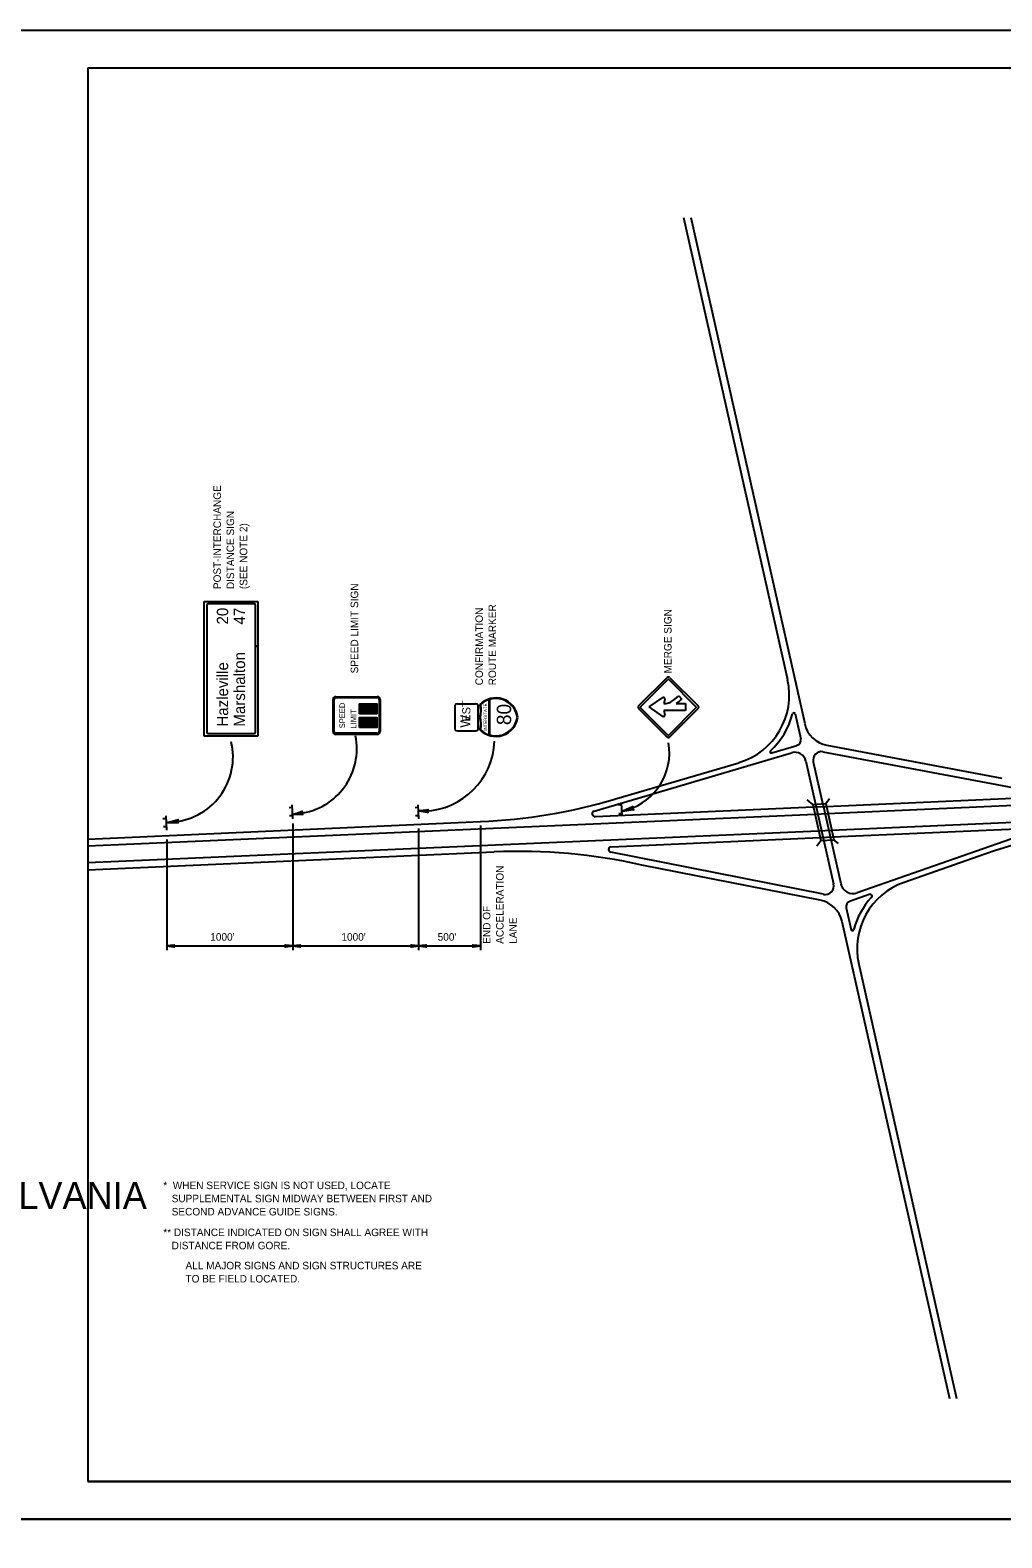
# Model space of a CAD drawing. Extents: x 644898 to 648326, y 298294 to 300670.
# Drawn here: x 645756 to 646144, y 300069 to 300670 of the extents above; entities that cross this region are included whole.
import ezdxf

# ---------------------------------------------------------------- set-up
doc = ezdxf.new("R2010")
doc.units = 0
for name, color, linetype in [('1', 7, 'Continuous'), ('2', 7, 'Continuous'), ('3', 7, 'Continuous'), ('XCS-GRID-MIN', 7, 'Continuous')]:
    doc.layers.add(name, color=color, linetype=linetype)

# ---------------------------------------------------------------- blocks, each defined once
blk = doc.blocks.new('RARROW')
at = {"layer": '3'}
blk.add_lwpolyline([(-2.2695, 0.285), (-2.184875, 0.12075), (0, 0), (-2.2695, 0.285), (-2.38575, 0.384625), (0, 0), (-2.183125, -0.108), (-2.262875, -0.2705), (0, 0), (-2.38575, -0.379125), (-2.262875, -0.2705)], dxfattribs=at)

msp = doc.modelspace()

# ---------------------------------------------------------------- linework, layer by layer
at = {"layer": '1'}
for p, q in [((645779.32, 300655.49), (646565.32, 300655.49)), ((645779.32, 300655.49), (645779.32, 300091.49)), ((646565.32, 300091.49), (645779.32, 300091.49)), ((645779.32, 300091.49), (646365.32, 300091.49))]:
    msp.add_line(p, q, dxfattribs=at)
at = {"layer": '2'}
for p, q in [((646016.95, 300595.74), (646058.45, 300411.37)), ((646019.95, 300595.74), (646065.32, 300393.87)), ((645825.82, 300388.87), (645825.82, 300442.62)), ((645825.82, 300442.62), (645847.2, 300442.62)), ((645826.82, 300441.12), (645826.82, 300390.37)), ((645845.7, 300441.62), (645827.32, 300441.62)), ((645846.2, 300424.75), (645846.2, 300441.12)), ((645847.2, 300442.62), (645847.2, 300424.75)), ((645846.2, 300424.75), (645847.2, 300424.75)), ((645847.2, 300424.75), (645846.2, 300424.75)), ((645846.2, 300390.37), (645846.2, 300424.75)), ((645847.2, 300424.75), (645847.2, 300388.87)), ((645836.45, 300415.74), (645836.45, 300415.74)), ((645999.07, 300400.87), (646010.45, 300412.24)), ((645999.82, 300400.49), (646010.7, 300411.37)), ((646011.07, 300411.37), (646021.95, 300400.49)), ((646011.45, 300412.24), (646022.82, 300400.87)), ((645877.2, 300390.74), (645877.2, 300403.49)), ((645877.57, 300390.74), (645877.57, 300403.49)), ((645878.32, 300404.49), (645894.82, 300404.49)), ((645878.32, 300404.24), (645894.82, 300404.24)), ((645891.7, 300397.74), (645887.7, 300401.74)), ((645892.45, 300397.74), (645888.45, 300401.74)), ((645893.07, 300397.74), (645889.07, 300401.74)), ((645893.82, 300397.74), (645889.82, 300401.74)), ((645894.45, 300397.74), (645890.45, 300401.74)), ((645894.7, 300398.24), (645891.2, 300401.74)), ((645894.7, 300398.99), (645891.95, 300401.74)), ((645894.7, 300399.62), (645892.7, 300401.74)), ((645894.7, 300400.24), (645893.32, 300401.74)), ((645894.7, 300400.99), (645894.07, 300401.74)), ((645895.57, 300403.49), (645895.57, 300390.74)), ((645895.95, 300403.49), (645895.95, 300390.74)), ((645925.95, 300391.49), (645925.95, 300401.24)), ((645926.82, 300401.74), (645933.95, 300401.74)), ((645934.95, 300401.24), (645934.95, 300391.49)), ((645935.95, 300401.37), (645935.95, 300401.37)), ((645939.45, 300389.37), (645939.45, 300403.49)), ((645939.7, 300389.37), (645939.7, 300403.49)), ((646003.32, 300400.49), (646008.7, 300404.24)), ((646009.57, 300403.49), (646009.07, 300401.87)), ((646009.07, 300401.87), (646009.45, 300401.87)), ((646014.07, 300401.87), (646017.82, 300401.87)), ((646015.07, 300404.87), (646016.32, 300403.62)), ((646017.82, 300401.87), (646017.82, 300399.12)), ((645886.57, 300396.99), (645886.57, 300396.99)), ((645890.95, 300397.74), (645887.7, 300401.12)), ((645890.2, 300397.74), (645887.7, 300400.37)), ((645889.57, 300397.74), (645887.7, 300399.74)), ((645888.95, 300397.74), (645887.7, 300398.99)), ((645888.2, 300397.74), (645887.7, 300398.24)), ((645891.7, 300392.24), (645887.7, 300396.24)), ((645890.95, 300392.24), (645887.7, 300395.62)), ((645892.45, 300392.24), (645888.45, 300396.24)), ((645893.07, 300392.24), (645889.07, 300396.24)), ((645893.82, 300392.24), (645889.82, 300396.24)), ((645894.45, 300392.24), (645890.45, 300396.24)), ((645894.7, 300392.74), (645891.2, 300396.24)), ((645894.7, 300393.49), (645891.95, 300396.24)), ((645894.7, 300394.12), (645892.7, 300396.24)), ((645894.7, 300394.74), (645893.32, 300396.24)), ((645894.7, 300395.49), (645894.07, 300396.24)), ((645930.45, 300396.37), (645930.45, 300396.37)), ((645935.95, 300396.37), (645935.95, 300396.37)), ((645943.32, 300396.37), (645943.32, 300396.37)), ((646010.45, 300388.49), (645999.07, 300399.87)), ((646010.7, 300389.24), (645999.82, 300400.12)), ((646008.7, 300396.74), (646003.32, 300400.49)), ((646017.82, 300399.12), (646009.07, 300399.12)), ((646009.07, 300399.12), (646009.57, 300397.49)), ((646021.95, 300400.12), (646011.07, 300389.24)), ((646021.95, 300400.12), (646011.07, 300389.24)), ((646022.82, 300399.87), (646011.45, 300388.49)), ((646061.57, 300397.74), (646063.82, 300387.74)), ((645827.32, 300389.87), (645845.7, 300389.87)), ((645894.82, 300389.99), (645878.32, 300389.99)), ((645894.82, 300389.49), (645878.32, 300389.49)), ((645890.2, 300392.24), (645887.7, 300394.87)), ((645889.57, 300392.24), (645887.7, 300394.24)), ((645888.95, 300392.24), (645887.7, 300393.49)), ((645888.2, 300392.24), (645887.7, 300392.74)), ((645933.95, 300390.87), (645926.82, 300390.87)), ((645935.95, 300391.37), (645935.95, 300391.37)), ((645847.2, 300388.87), (645825.82, 300388.87)), ((646052.2, 300382.12), (646062.2, 300385.12)), ((646074.2, 300385.24), (646143.95, 300372.12)), ((645981.32, 300358.87), (646060.07, 300382.24)), ((645989.45, 300363.74), (646039.07, 300378.24)), ((646065.79, 300378.91), (646069.57, 300361.74)), ((646068.74, 300378.57), (646072.57, 300361.62)), ((646072.57, 300382.62), (646157.57, 300366.62)), ((646074.45, 300357.99), (646565.32, 300379.71)), ((646075.95, 300351.37), (646565.32, 300372.83)), ((645860.7, 300360.37), (645859.7, 300360.24)), ((645860.7, 300361.37), (645860.95, 300355.87)), ((645910.95, 300360.37), (645909.95, 300360.24)), ((645910.95, 300361.37), (645911.2, 300355.87)), ((645981.7, 300356.74), (646068.82, 300360.62)), ((645992.07, 300361.37), (645991.07, 300361.24)), ((645992.07, 300362.37), (645992.32, 300356.87)), ((646068.57, 300361.62), (646066.32, 300363.37)), ((646068.57, 300361.62), (646073.7, 300361.99)), ((646068.57, 300361.62), (646071.82, 300347.24)), ((646068.82, 300360.62), (646073.82, 300360.74)), ((646069.57, 300361.74), (646076.82, 300329.87)), ((646072.57, 300361.87), (646079.7, 300329.99)), ((646073.7, 300361.99), (646075.2, 300363.99)), ((646073.7, 300361.99), (646076.95, 300347.49)), ((646073.82, 300360.74), (646157.45, 300364.49)), ((645779.32, 300345.08), (646069.45, 300357.74)), ((645779.32, 300347.71), (645935.95, 300354.74)), ((645810.45, 300355.87), (645809.32, 300355.87)), ((645810.45, 300356.99), (645810.7, 300351.37)), ((645860.95, 300356.99), (645859.82, 300356.99)), ((645861.07, 300353.99), (645861.07, 300303.49)), ((645911.2, 300356.99), (645910.07, 300356.99)), ((645911.32, 300353.62), (645911.32, 300353.62)), ((645935.95, 300353.24), (645935.95, 300303.49)), ((645992.32, 300357.87), (645991.2, 300357.87)), ((646069.45, 300357.74), (646074.45, 300357.99)), ((645779.32, 300338.46), (646070.82, 300351.12)), ((645810.57, 300352.62), (645809.57, 300352.62)), ((645810.82, 300349.24), (645810.82, 300349.24)), ((645810.82, 300347.62), (645810.82, 300303.49)), ((645911.32, 300351.99), (645911.32, 300303.49)), ((645988.2, 300344.62), (646071.45, 300348.37)), ((646070.2, 300345.12), (646071.82, 300347.24)), ((646070.82, 300351.12), (646075.95, 300351.37)), ((646071.45, 300348.37), (646076.57, 300348.62)), ((646071.82, 300347.24), (646076.95, 300347.49)), ((646076.57, 300348.62), (646152.95, 300351.99)), ((646078.82, 300345.99), (646076.95, 300347.49)), ((646153.32, 300349.74), (646086.24, 300326.29)), ((645779.32, 300335.46), (645941.45, 300342.62)), ((646072.82, 300325.74), (645987.95, 300342.49)), ((646137.2, 300341.74), (646104.95, 300330.49)), ((646071.45, 300323.37), (646000.32, 300337.37)), ((646091, 300325.61), (646083.2, 300322.87)), ((646081.84, 300320.31), (646083.82, 300311.62)), ((646080.2, 300314.87), (646123.07, 300124.62)), ((645810.82, 300305.12), (645861.07, 300305.12)), ((645861.07, 300305.12), (645911.32, 300305.12)), ((645911.32, 300305.12), (645935.95, 300305.12)), ((646086.95, 300297.87), (646125.82, 300124.62))]:
    msp.add_line(p, q, dxfattribs=at)
for points in [[(645887.7, 300397.74), (645887.7, 300401.74), (645894.7, 300401.74), (645894.7, 300397.74)], [(645887.7, 300392.24), (645887.7, 300396.24), (645894.7, 300396.24), (645894.7, 300392.24)]]:
    msp.add_lwpolyline(points, close=True, dxfattribs=at)
for points in [[(645914.82, 300358.49), (645914.7, 300358.74), (645911.32, 300358.99), (645914.82, 300358.49), (645915.07, 300358.37), (645911.32, 300358.99), (645914.7, 300359.12), (645914.82, 300359.37), (645911.32, 300358.99), (645915.07, 300359.62), (645914.82, 300359.37)], [(645996.95, 300359.62), (645996.57, 300359.87), (645992.82, 300358.87), (645996.95, 300359.62), (645997.2, 300359.49), (645992.82, 300358.87), (645996.57, 300360.24), (645996.57, 300360.62), (645992.82, 300358.87), (645996.7, 300360.74), (645996.57, 300360.62)], [(645815.33, 300354.45), (645815.08, 300354.57), (645811.2, 300354.45), (645815.33, 300354.45), (645815.45, 300354.2), (645811.2, 300354.45), (645815.08, 300355.07), (645815.2, 300355.32), (645811.2, 300354.45), (645815.33, 300355.57), (645815.2, 300355.32)], [(645864.84, 300357.69), (645864.67, 300357.91), (645861.31, 300357.57), (645864.84, 300357.69), (645865.11, 300357.61), (645861.31, 300357.57), (645864.61, 300358.28), (645864.69, 300358.55), (645861.31, 300357.57), (645864.89, 300358.84), (645864.69, 300358.55)], [(645813.68, 300304.76), (645813.57, 300304.97), (645810.82, 300305.12), (645813.68, 300304.76), (645813.82, 300304.64), (645810.82, 300305.12), (645813.57, 300305.26), (645813.67, 300305.46), (645810.82, 300305.12), (645813.82, 300305.6), (645813.67, 300305.46)], [(645858.22, 300305.48), (645858.33, 300305.27), (645861.07, 300305.12), (645858.22, 300305.48), (645858.07, 300305.6), (645861.07, 300305.12), (645858.33, 300304.98), (645858.23, 300304.78), (645861.07, 300305.12), (645858.07, 300304.64), (645858.23, 300304.78)], [(645863.93, 300304.76), (645863.82, 300304.97), (645861.07, 300305.12), (645863.93, 300304.76), (645864.07, 300304.64), (645861.07, 300305.12), (645863.82, 300305.26), (645863.92, 300305.46), (645861.07, 300305.12), (645864.07, 300305.6), (645863.92, 300305.46)], [(645908.47, 300305.48), (645908.58, 300305.27), (645911.32, 300305.12), (645908.47, 300305.48), (645908.32, 300305.6), (645911.32, 300305.12), (645908.58, 300304.98), (645908.48, 300304.78), (645911.32, 300305.12), (645908.32, 300304.64), (645908.48, 300304.78)], [(645914.18, 300304.76), (645914.07, 300304.97), (645911.32, 300305.12), (645914.18, 300304.76), (645914.32, 300304.64), (645911.32, 300305.12), (645914.07, 300305.26), (645914.17, 300305.46), (645911.32, 300305.12), (645914.32, 300305.6), (645914.17, 300305.46)], [(645933.09, 300305.48), (645933.2, 300305.27), (645935.95, 300305.12), (645933.09, 300305.48), (645932.95, 300305.6), (645935.95, 300305.12), (645933.2, 300304.98), (645933.1, 300304.78), (645935.95, 300305.12), (645932.95, 300304.64), (645933.1, 300304.78)]]:
    msp.add_lwpolyline(points, dxfattribs=at)
for centre, radius, start, end in [((645827.32, 300441.12), 0.5, 90, 180), ((645845.7, 300441.12), 0.5, 0, 90), ((646010.96, 300411.73), 0.699, 45, 135), ((646010.96, 300411.73), 0.699, 45, 135), ((646010.89, 300411.2), 0.25, 45, 135), ((646031.18, 300405.19), 27.99, 286.46389, 12.68034), ((645878.32, 300403.43), 1.13, 90, 180), ((645878.32, 300403.43), 0.75, 90, 180), ((645894.82, 300403.43), 1.13, 0, 90), ((645894.82, 300403.43), 0.75, 0, 90), ((645942.09, 300395.14), 8.94, 8.1301, 135), ((645925.81, 300398.94), 10.28, 345.74997, 14.25003), ((645925.81, 300398.94), 10.46, 346.01104, 13.6595), ((645942.09, 300395.14), 8.75, 107.54623, 134.30764), ((645942.09, 300395.14), 8.69, 8.1301, 105.95434), ((646009.01, 300403.7), 0.582, 343.79783, 121.66937), ((646009.39, 300406.54), 4.73, 269.77573, 299.88968), ((646003.69, 300416.71), 16.39, 299.43702, 313.88494), ((646003.38, 300417.09), 18.68, 305.14146, 313.88923), ((645925.81, 300393.88), 10.28, 345.74997, 14.25003), ((645942.09, 300397.67), 8.94, 225, 351.8699), ((645925.81, 300393.88), 10.46, 346.3405, 13.98896), ((645942.09, 300397.67), 8.69, 254.04566, 351.8699), ((645999.59, 300400.36), 0.699, 135, 225), ((645999.59, 300400.36), 0.699, 135, 225), ((645999.99, 300400.31), 0.25, 135, 225), ((646009.01, 300397.29), 0.582, 238.443, 16.08981), ((646021.76, 300400.33), 0.25, 309.28941, 45), ((646022.33, 300400.36), 0.699, 315, 45), ((646022.33, 300400.36), 0.699, 315, 45), ((646031.18, 300405.19), 30.23, 312.60339, 345.66334), ((646061.02, 300397.55), 0.566, 20.17087, 164.59507), ((645827.32, 300390.37), 0.5, 180, 270), ((645845.7, 300390.37), 0.5, 270, 360), ((645878.32, 300390.68), 1.13, 180, 270), ((645878.32, 300390.68), 0.75, 180, 270), ((645894.82, 300390.68), 1.13, 270, 0), ((645894.82, 300390.68), 0.75, 270, 0), ((645942.09, 300397.67), 8.75, 225.69236, 252.45377), ((646010.89, 300389.41), 0.25, 225, 315), ((646010.89, 300389.41), 0.25, 225, 315), ((646076.24, 300396.25), 11.2, 192.68035, 259.39124), ((645811.33, 300380.5), 25.94, 272.1007, 13.60606), ((645860.71, 300383.75), 25.94, 277.01253, 11.46002), ((645912.59, 300387.97), 29.05, 272.21751, 357.78249), ((645987.59, 300382.15), 23.75, 286.93284, 9.61942), ((646010.96, 300388.99), 0.699, 225, 315), ((646010.96, 300388.99), 0.699, 225, 315), ((646061.6, 300387.32), 2.24, 286.46377, 12.68123), ((646051.95, 300382.59), 0.455, 130.53264, 302.14851), ((646061.42, 300377.93), 4.48, 12.68, 106.46376), ((646072.01, 300379.31), 3.36, 79.39121, 192.6799), ((645926.08, 300578.45), 223.94, 272.5187, 286.46393), ((645981.66, 300357.86), 1.12, 106.46381, 272.51876), ((646211.06, 300130.34), 223.94, 92.51875, 109.26329), ((645951.28, 300118.92), 223.94, 77.3419, 92.51875), ((645988.23, 300343.58), 1.12, 92.51875, 257.34197), ((646073.46, 300329.14), 3.5, 259.33581, 12.57469), ((646084.61, 300331.02), 5, 192.27026, 289.0723), ((646114.19, 300304.06), 27.99, 109.26337, 192.68034), ((646069.28, 300312.41), 11.2, 12.68046, 78.84184), ((646114.19, 300304.06), 30.23, 137.59817, 165.05653), ((646091.44, 300325.02), 0.739, 298.83597, 127.17309), ((646084.03, 300320.8), 2.24, 109.26352, 192.68012), ((646084.36, 300311.9), 0.623, 204.68777, 356.14813)]:
    msp.add_arc(centre, radius, start, end, dxfattribs=at)
for centre, major_axis, start_param, end_param in [((645926.84, 300401.17), (-0.896, 0), 4.712389, 6.283185), ((645934.01, 300401.17), (-0.896, 0), 3.141593, 4.712389), ((645926.84, 300391.5), (0.896, 0), 3.141593, 4.712389), ((645934.01, 300391.5), (0.896, 0), 4.712389, 6.283185)]:
    msp.add_ellipse(centre, major_axis=major_axis, ratio=0.6, start_param=start_param, end_param=end_param, dxfattribs=at)
at = {"layer": 'XCS-GRID-MIN'}
for points in [[(645739.32, 300670.49), (646580.32, 300670.49), (646580.32, 300076.49), (645739.32, 300076.49)], [(645739.32, 300076.49), (646580.32, 300076.49), (646580.32, 299482.49), (645739.32, 299482.49)]]:
    msp.add_lwpolyline(points, close=True, dxfattribs=at)

# ---------------------------------------------------------------- block references
at = {"layer": '2', "xscale": 1.2574347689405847, "yscale": 1.3092961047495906}
msp.add_blockref('RARROW', (645861.07, 300305.12), dxfattribs=at)

# ---------------------------------------------------------------- texts
at = {"layer": '1'}
msp.add_text('COMMONWEALTH OF PENNSYLVANIA', height=10.7828, dxfattribs=at).set_placement((645536.92, 300200.22))
at = {"layer": '2'}
for s, height, p in [('POST-INTERCHANGE', 3, (645832.45, 300447.49)), ('DISTANCE SIGN', 3, (645837.7, 300447.49)), ('(SEE NOTE 2)', 3, (645842.95, 300447.49)), ('SPEED LIMIT SIGN', 3, (645887.2, 300413.87)), ('20', 4.5, (645835.32, 300433.37)), ('47', 4.5, (645842.07, 300433.37)), ('CONFIRMATION', 3, (645936.95, 300409.12)), ('ROUTE MARKER', 3, (645942.2, 300409.12)), ('MERGE SIGN', 3, (646012.2, 300413.87)), ('Marshalton     ', 4.5, (645842.07, 300392.62)), ('Hazleville     ', 4.5, (645835.32, 300392.62)), ('SPEED', 2.249, (645881.95, 300391.99)), ('EST', 3.25, (645931.95, 300394.62)), ('INTERSTATE', 1.264, (645938.57, 300390.99)), ('80', 5.69, (645948.2, 300393.24)), ('LIMIT', 2.249, (645886.45, 300391.87)), ('W', 4, (645931.95, 300392.24)), ('ACCELERATION', 3, (645945.2, 300305.99)), ('END OF', 3, (645939.95, 300305.99)), ('LANE', 3, (645950.45, 300305.99))]:
    msp.add_text(s, height=height, rotation=90, dxfattribs=at).set_placement(p)
for s, p in [("1000'", (645828.19, 300307.24)), ("1000'", (645880.51, 300307.24)), ("500'", (645918.9, 300307.24)), ('*  WHEN SERVICE SIGN IS NOT USED, LOCATE', (645809.45, 300208.12)), ('   SUPPLEMENTAL SIGN MIDWAY BETWEEN FIRST AND', (645809.45, 300202.87)), ('   SECOND ADVANCE GUIDE SIGNS.', (645809.45, 300197.62)), ('** DISTANCE INDICATED ON SIGN SHALL AGREE WITH', (645809.45, 300189.37)), ('   DISTANCE FROM GORE.', (645809.45, 300184.12)), ('ALL MAJOR SIGNS AND SIGN STRUCTURES ARE', (645818.32, 300176.12)), ('TO BE FIELD LOCATED.', (645818.32, 300170.87))]:
    msp.add_text(s, height=3, dxfattribs=at).set_placement(p)

doc.saveas('drawing.dxf')
